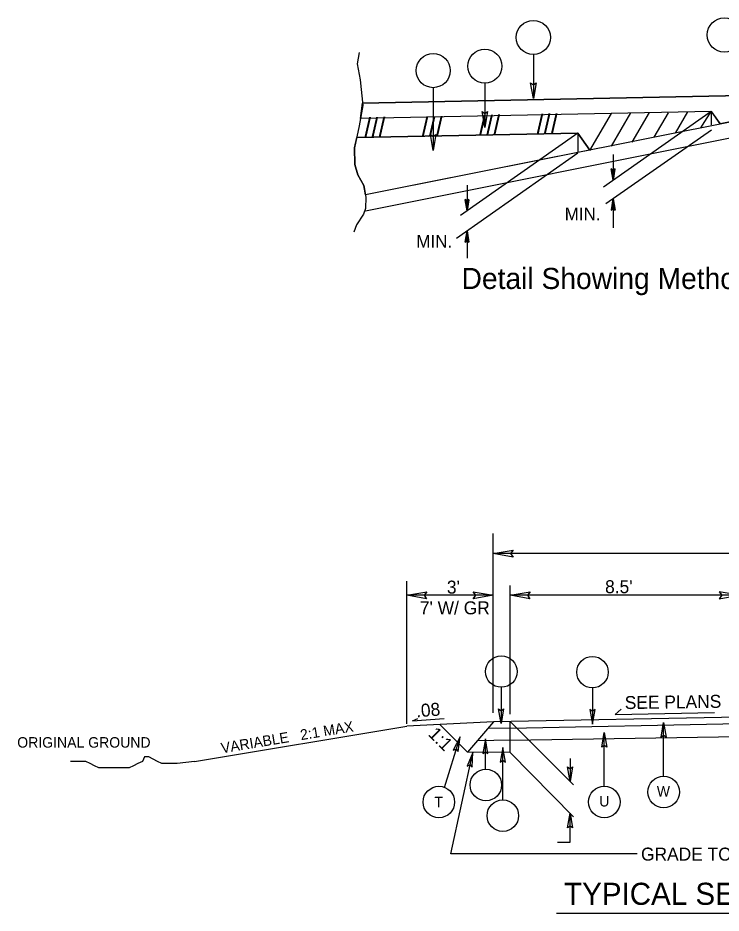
# Model space of a CAD drawing. Extents: x 106738.7 to 106779.9, y 105993.5 to 106034.9.
# Drawn here: x 106752.63 to 106760.11, y 105993.9 to 106003.44 of the extents above; entities that cross this region are included whole.
import ezdxf

# ---------------------------------------------------------------- set-up
doc = ezdxf.new("R2010")
doc.units = 0
for name, color, linetype in [('Old_Level_1', 7, 'Continuous'), ('Old_Level_11', 7, 'Continuous'), ('Old_Level_2', 7, 'Continuous'), ('Typical Detail Wedge2 CELL', 7, 'Continuous'), ('Typical Hinge Slope Arterial CELL', 7, 'Continuous'), ('Typical ID Circle CELL', 7, 'Continuous'), ('Typical Terminator CELL', 7, 'Continuous'), ('Typical Text General CELL', 7, 'Continuous')]:
    doc.layers.add(name, color=color, linetype=linetype)

msp = doc.modelspace()

# ---------------------------------------------------------------- linework, layer by layer
at = {"layer": 'Old_Level_1'}
for p, q in [((106757.6861, 105995.9385), (106756.7637, 105995.8954)), ((106757.4123, 105995.615), (106757.1155, 105995.9118)), ((106757.6861, 105995.9385), (106757.4123, 105995.615)), ((106758.5386, 105995.2681), (106757.8647, 105995.942)), ((106757.233, 105994.5341), (106757.4667, 105995.6149)), ((106758.5386, 105994.9292), (106757.8647, 105995.6139)), ((106759.2159, 105994.5341), (106757.233, 105994.5341)), ((106758.3591, 105993.9025), (106762.2247, 105993.9025))]:
    msp.add_line(p, q, dxfattribs=at)
for points in [[(106759.0467, 105996.0736), (106758.9838, 105996.0189), (106760.0401, 105996.0401)], [(106756.8267, 105995.9502), (106757.1621, 105995.977)], [(106756.8267, 105995.9502), (106756.8838, 105995.976)]]:
    msp.add_lwpolyline(points, dxfattribs=at)
at = {"layer": 'Old_Level_11'}
for p, q in [((106757.6841, 105996.0355), (106757.6841, 105997.9456)), ((106762.8635, 105997.7318), (106757.6841, 105997.7318)), ((106756.7637, 105995.92), (106756.7637, 105997.4384)), ((106757.8647, 105996.0231), (106757.8647, 105997.393)), ((106757.6841, 105997.2879), (106756.7637, 105997.2879)), ((106760.3031, 105997.2878), (106757.8647, 105997.2879)), ((106757.769, 105996.3072), (106757.769, 105995.9211)), ((106758.7414, 105996.3009), (106758.7414, 105995.9147)), ((106759.4988, 105995.3604), (106759.4988, 105995.9313)), ((106757.1664, 105995.2418), (106757.3317, 105995.7811)), ((106757.602, 105995.4364), (106757.602, 105995.7578)), ((106758.8664, 105995.254), (106758.8664, 105995.825)), ((106757.7871, 105995.108), (106757.787, 105995.6666)), ((106758.5024, 105995.5481), (106758.5024, 105995.3043)), ((106758.5024, 105994.6558), (106758.5024, 105994.9659)), ((106758.4988, 105994.6558), (106758.3706, 105994.6558))]:
    msp.add_line(p, q, dxfattribs=at)
for points in [[(106757.8957, 105997.6954), (106757.6841, 105997.7318), (106757.8969, 105997.7695), (106757.8699, 105997.7318)], [(106756.9753, 105997.2514), (106756.7637, 105997.2879), (106756.9765, 105997.3255), (106756.9494, 105997.2878)], [(106757.4726, 105997.3243), (106757.6841, 105997.2879), (106757.4714, 105997.2502), (106757.4984, 105997.2879)], [(106758.0763, 105997.2514), (106757.8647, 105997.2879), (106758.0775, 105997.3255), (106758.0505, 105997.2879)], [(106760.0914, 105997.2514), (106760.3031, 105997.2878), (106760.0903, 105997.3255), (106760.1173, 105997.2878)], [(106757.7959, 105996.0767), (106757.769, 105995.9211), (106757.7414, 105996.0775), (106757.769, 105996.0577)], [(106758.7146, 105996.0703), (106758.7414, 105995.9147), (106758.7691, 105996.0711), (106758.7414, 105996.0514)], [(106759.4719, 105995.7758), (106759.4988, 105995.9313), (106759.5264, 105995.7749), (106759.4988, 105995.7947)], [(106757.3118, 105995.6245), (106757.3317, 105995.7811), (106757.2594, 105995.6396), (106757.2917, 105995.6504)], [(106757.6289, 105995.6022), (106757.602, 105995.7578), (106757.5744, 105995.6014), (106757.602, 105995.6211)], [(106758.8396, 105995.6694), (106758.8664, 105995.825), (106758.8941, 105995.6686), (106758.8664, 105995.6884)], [(106757.8139, 105995.511), (106757.787, 105995.6666), (106757.7594, 105995.5102), (106757.7871, 105995.5299)], [(106757.4599, 105995.4571), (106757.4667, 105995.6149), (106757.4065, 105995.4678), (106757.4377, 105995.4813)], [(106758.5292, 105995.4599), (106758.5024, 105995.3043), (106758.4748, 105995.4607), (106758.5024, 105995.441)], [(106758.4756, 105994.8103), (106758.5024, 105994.9659), (106758.5301, 105994.8095), (106758.5024, 105994.8292)]]:
    msp.add_lwpolyline(points, close=True, dxfattribs=at)
for centre in [(106757.7713, 105996.4757), (106758.7414, 105996.4689), (106757.6064, 105995.2673), (106759.4988, 105995.1923), (106757.1061, 105995.085), (106758.8664, 105995.086), (106757.7871, 105994.9399)]:
    msp.add_circle(centre, 0.168, dxfattribs=at)
at = {"layer": 'Old_Level_2'}
for p, q in [((106760.3027, 105995.9908), (106757.6861, 105995.9385)), ((106757.8647, 105995.8723), (106757.626, 105995.8675)), ((106757.8647, 105995.6139), (106757.8647, 105995.942)), ((106757.8647, 105995.8718), (106760.3031, 105995.9206)), ((106757.8647, 105995.7453), (106760.3031, 105995.7824)), ((106757.8647, 105995.7462), (106757.5174, 105995.7392)), ((106757.8647, 105995.6139), (106757.4123, 105995.615))]:
    msp.add_line(p, q, dxfattribs=at)
at = {"layer": 'Typical Detail Wedge2 CELL'}
for p, q in [((106756.2711, 106002.3679), (106756.2944, 106002.5315)), ((106760.3667, 106002.6128), (106756.2944, 106002.5315)), ((106756.2944, 106002.5315), (106760.3667, 106002.6128)), ((106760.0095, 106002.4426), (106756.2711, 106002.3679)), ((106760.0095, 106002.4426), (106756.2711, 106002.3679)), ((106760.0048, 106002.4396), (106758.8574, 106001.6359)), ((106759.3458, 106002.4293), (106759.162, 106002.1141)), ((106759.5485, 106002.4288), (106759.3961, 106002.1678)), ((106759.7529, 106002.4393), (106759.6201, 106002.2116)), ((106759.8937, 106002.2685), (106760.0042, 106002.4411)), ((106760.0042, 106002.4411), (106760.0042, 106002.2992)), ((106760.1009, 106002.3084), (106760.0095, 106002.4426)), ((106760.0095, 106002.4382), (106760.1009, 106002.3084)), ((106760.3728, 106002.3625), (106756.3249, 106001.5527)), ((106758.9414, 106002.4212), (106758.71, 106002.0246)), ((106759.1446, 106002.4254), (106758.9398, 106002.0737)), ((106760.3607, 106002.3625), (106760.1009, 106002.3084)), ((106760.0075, 106002.2432), (106758.8847, 106001.457)), ((106758.5853, 106002.2099), (106756.2315, 106002.1628)), ((106756.2315, 106002.1628), (106758.5853, 106002.2099)), ((106760.3652, 106002.1882), (106756.3235, 106001.3798)), ((106758.5853, 106002.2099), (106757.3355, 106001.3347)), ((106758.7133, 106002.03), (106758.5853, 106002.2099)), ((106758.5853, 106002.2099), (106758.5853, 106002.0045)), ((106758.5853, 106002.2099), (106758.713, 106002.0304)), ((106758.5842, 106001.9981), (106757.2922, 106001.0889)), ((106758.5853, 106002.0048), (106758.1753, 106001.9228)), ((106758.713, 106002.0304), (106758.5853, 106002.0048)), ((106758.9619, 106001.9822), (106758.9619, 106001.7093)), ((106758.1753, 106001.9228), (106756.3249, 106001.5527)), ((106758.9619, 106001.7093), (106758.9408, 106001.8289)), ((106758.9619, 106001.8133), (106758.9408, 106001.8289)), ((106758.9619, 106001.7093), (106758.9438, 106001.8267)), ((106758.9468, 106001.8244), (106758.9619, 106001.7093)), ((106758.9619, 106001.7093), (106758.9498, 106001.8223)), ((106758.9529, 106001.8201), (106758.9619, 106001.7093)), ((106758.9619, 106001.7093), (106758.9559, 106001.8178)), ((106758.9589, 106001.8156), (106758.9619, 106001.7093)), ((106758.9619, 106001.7093), (106758.9832, 106001.8289)), ((106758.9832, 106001.8289), (106758.9619, 106001.8133)), ((106758.9802, 106001.8267), (106758.9619, 106001.7093)), ((106758.9619, 106001.7093), (106758.9769, 106001.8244)), ((106758.9739, 106001.8223), (106758.9619, 106001.7093)), ((106758.9619, 106001.7093), (106758.9709, 106001.8201)), ((106758.9679, 106001.8178), (106758.9619, 106001.7093)), ((106758.9619, 106001.7093), (106758.9649, 106001.8156)), ((106758.9619, 106001.8133), (106758.9619, 106001.7093)), ((106757.4058, 106001.656), (106757.4058, 106001.3838)), ((106757.4058, 106001.3838), (106757.3846, 106001.5036)), ((106757.4058, 106001.4882), (106757.3846, 106001.5036)), ((106757.4058, 106001.3838), (106757.3876, 106001.5015)), ((106757.3908, 106001.4991), (106757.4058, 106001.3838)), ((106757.4058, 106001.3838), (106757.3938, 106001.497)), ((106757.3968, 106001.4949), (106757.4058, 106001.3838)), ((106757.4058, 106001.3838), (106757.3998, 106001.4926)), ((106757.4028, 106001.4904), (106757.4058, 106001.3838)), ((106757.4058, 106001.3838), (106757.4269, 106001.5036)), ((106757.4269, 106001.5036), (106757.4058, 106001.4882)), ((106757.4239, 106001.5015), (106757.4058, 106001.3838)), ((106757.4058, 106001.3838), (106757.4209, 106001.4991)), ((106757.4179, 106001.497), (106757.4058, 106001.3838)), ((106757.4058, 106001.3838), (106757.4148, 106001.4949)), ((106757.412, 106001.4926), (106757.4058, 106001.3838)), ((106757.4058, 106001.3838), (106757.4088, 106001.4904)), ((106757.4058, 106001.4882), (106757.4058, 106001.3838)), ((106758.9619, 106001.5111), (106758.9408, 106001.3913)), ((106758.9438, 106001.3937), (106758.9619, 106001.5111)), ((106758.9619, 106001.5111), (106758.9468, 106001.3958)), ((106758.9498, 106001.3982), (106758.9619, 106001.5111)), ((106758.9619, 106001.5111), (106758.9529, 106001.4003)), ((106758.9559, 106001.4024), (106758.9619, 106001.5111)), ((106758.9619, 106001.5111), (106758.9589, 106001.4046)), ((106758.9619, 106001.5111), (106758.9619, 106001.2037)), ((106758.9619, 106001.5111), (106758.9832, 106001.3913)), ((106758.9619, 106001.4069), (106758.9619, 106001.5111)), ((106758.9649, 106001.4046), (106758.9619, 106001.5111)), ((106758.9619, 106001.5111), (106758.9679, 106001.4024)), ((106758.9709, 106001.4003), (106758.9619, 106001.5111)), ((106758.9619, 106001.5111), (106758.9739, 106001.3982)), ((106758.9769, 106001.3958), (106758.9619, 106001.5111)), ((106758.9619, 106001.5111), (106758.9802, 106001.3937)), ((106758.9408, 106001.3913), (106758.9619, 106001.4069)), ((106758.9619, 106001.4069), (106758.9832, 106001.3913)), ((106757.4058, 106001.1685), (106757.3846, 106001.0487)), ((106757.3879, 106001.051), (106757.4058, 106001.1685)), ((106757.4058, 106001.1685), (106757.3908, 106001.0532)), ((106757.3938, 106001.0555), (106757.4058, 106001.1685)), ((106757.4058, 106001.1685), (106757.3968, 106001.0577)), ((106757.3998, 106001.0598), (106757.4058, 106001.1685)), ((106757.4058, 106001.1685), (106757.4028, 106001.0619)), ((106757.4058, 106001.1685), (106757.4058, 106000.8775)), ((106757.4058, 106001.1685), (106757.4269, 106001.0487)), ((106757.4058, 106001.0643), (106757.4058, 106001.1685)), ((106757.4088, 106001.0619), (106757.4058, 106001.1685)), ((106757.4058, 106001.1685), (106757.412, 106001.0598)), ((106757.4149, 106001.0577), (106757.4058, 106001.1685)), ((106757.4058, 106001.1685), (106757.4179, 106001.0555)), ((106757.4209, 106001.0532), (106757.4058, 106001.1685)), ((106757.4058, 106001.1685), (106757.4239, 106001.051)), ((106757.3846, 106001.0487), (106757.4058, 106001.0643)), ((106757.4058, 106001.0643), (106757.4269, 106001.0487))]:
    msp.add_line(p, q, dxfattribs=at)
for points in [[(106756.2565, 106003.069), (106756.2348, 106002.9497), (106756.2674, 106002.78), (106756.2961, 106002.5055), (106756.2565, 106002.2887), (106756.2096, 106002.0539), (106756.2132, 106001.8768), (106756.2421, 106001.765), (106756.3072, 106001.6528), (106756.3288, 106001.5301), (106756.3252, 106001.4073), (106756.3035, 106001.3494), (106756.2277, 106001.2338), (106756.2024, 106001.1543)], [(106756.3247, 106001.5527), (106756.3072, 106001.6528), (106756.2421, 106001.765), (106756.2132, 106001.8768), (106756.2096, 106002.0539), (106756.2313, 106002.1628)]]:
    msp.add_lwpolyline(points, dxfattribs=at)
at = {"layer": 'Typical Hinge Slope Arterial CELL'}
msp.add_line((106754.5063, 105995.5191), (106756.7637, 105995.8954), dxfattribs=at)
msp.add_lwpolyline([(106754.5063, 105995.5191), (106754.3208, 105995.496), (106754.2745, 105995.496), (106754.2049, 105995.496), (106754.1585, 105995.496), (106754.1122, 105995.5191), (106754.0658, 105995.5424), (106754.0195, 105995.5656), (106753.9731, 105995.5656), (106753.9498, 105995.5191), (106753.9035, 105995.496), (106753.8571, 105995.4728), (106753.8108, 105995.4497), (106753.7644, 105995.4497), (106753.7181, 105995.4497), (106753.6717, 105995.4497), (106753.6253, 105995.4497), (106753.579, 105995.4497), (106753.5326, 105995.4497), (106753.4863, 105995.4497), (106753.4399, 105995.4728), (106753.3936, 105995.496), (106753.3472, 105995.5191), (106753.2776, 105995.5191), (106753.2312, 105995.5191), (106753.1849, 105995.5191)], dxfattribs=at)
at = {"layer": 'Typical ID Circle CELL'}
for p, q in [((106758.1119, 106003.0483), (106758.1119, 106002.5782)), ((106757.5958, 106002.7423), (106757.5958, 106002.2722)), ((106757.0458, 106002.6951), (106757.0458, 106002.0267))]:
    msp.add_line(p, q, dxfattribs=at)
for centre in [(106758.1119, 106003.2302), (106760.1457, 106003.2564), (106757.5958, 106002.9242), (106757.0457, 106002.877)]:
    msp.add_circle(centre, 0.1819, dxfattribs=at)
at = {"layer": 'Typical Terminator CELL'}
for points in [[(106758.1409, 106002.7466), (106758.1119, 106002.5782), (106758.0819, 106002.7476), (106758.1119, 106002.7261)], [(106757.6248, 106002.4407), (106757.5958, 106002.2722), (106757.5659, 106002.4416), (106757.5958, 106002.4201)], [(106757.0748, 106002.1951), (106757.0458, 106002.0267), (106757.0158, 106002.196), (106757.0458, 106002.1745)]]:
    msp.add_lwpolyline(points, close=True, dxfattribs=at)

# ---------------------------------------------------------------- texts
at = {"layer": 'Old_Level_1'}
for s, height, rotation, p in [('.08', 0.13831, 4.57392, (106756.8691, 105995.9873)), ('SEE PLANS', 0.13831, 0.79348, (106759.0858, 105996.0755)), ('1:1', 0.13831, 315, (106756.9855, 105995.8007)), ('W', 0.1107, 360, (106759.4264, 105995.1444)), ('T', 0.1107, 359.85996, (106757.0597, 105995.0305)), ('U', 0.1107, 360, (106758.814, 105995.0381)), ('GRADE TO THIS LINE', 0.13831, 360, (106759.2579, 105994.4615)), ('TYPICAL SECTION NO. 1', 0.235113, 360, (106758.4392, 105993.9905))]:
    msp.add_text(s, height=height, rotation=rotation, dxfattribs=at).set_placement(p)
at = {"layer": 'Old_Level_11'}
for s, rotation, p in [("3'", 0, (106757.1916, 105997.3059)), ("8.5'", 360, (106758.8755, 105997.3104)), ("7' W/ GR ", 0, (106756.9039, 105997.085))]:
    msp.add_text(s, height=0.13831, rotation=rotation, dxfattribs=at).set_placement(p)
at = {"layer": 'Typical Detail Wedge2 CELL'}
for height, rotation, p in [(0.20422, 1.14473, (106756.3125, 106002.1656)), (0.20423, 1.14639, (106756.9228, 106002.1728)), (0.20414, 1.14453, (106757.5346, 106002.1908)), (0.20415, 1.14629, (106758.1469, 106002.2033))]:
    msp.add_text('/// ', height=height, rotation=rotation, dxfattribs=at).set_placement(p)
for p in [(106758.4456, 106001.2818), (106756.866, 106000.9901)]:
    msp.add_text('MIN.', height=0.13547, dxfattribs=at).set_placement(p)
at = {"layer": 'Typical Hinge Slope Arterial CELL'}
for s, rotation, p in [('VARIABLE   2:1 MAX ', 9.46256, (106754.7965, 105995.6037)), ('ORIGINAL GROUND', 360, (106752.6183, 105995.665))]:
    msp.add_text(s, height=0.111697, rotation=rotation, dxfattribs=at).set_placement(p)
at = {"layer": 'Typical Text General CELL'}
msp.add_text('Detail Showing Method of Wedging No. 1', height=0.224569, dxfattribs=at).set_placement((106757.3476, 106000.5507))

doc.saveas('drawing.dxf')
